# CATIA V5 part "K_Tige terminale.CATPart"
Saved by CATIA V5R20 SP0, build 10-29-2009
Part number: Tige terminale
Property "Diamètre joint": 20 mm
Bounding box of the stored display mesh (mm): x -19.98 to 19.98, y -10 to 10, z 0 to 740
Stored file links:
  C:\Users\thinkmotion1\Desktop\Khaled_IAO_Pack2\Problemes\IAO_2010_1405_jpalas\IAO_PALAS\Khaled_Palas\K_Tige terminale.CATPart
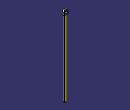
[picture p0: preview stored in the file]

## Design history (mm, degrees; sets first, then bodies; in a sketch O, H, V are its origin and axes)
Body1 (main body)
  Sketch1 on zx-plane, origin (0, 0, 0), H (0, 0, 1), V (1, 0, 0)
    point P1 (740, 0)
    line L1 (740, 0) -> (0, 0)
    line L2 (0, 0) -> (0, 10)
    line L3 (0, 10) -> (700, 10)
    line L4 (700, 10) -> (700, 20)
    line L5 (700, 20) -> (720, 20)
    arc A1 centre (720, 0) radius 20 from (740, 0) to (720, 20) ccw
    point P7 (720, 0)
    length L5 = 20
    length L3 = 700
    distance L3 L1 = 10
    distance L5 L1 = 20
    radius A1 = 20
    coincidence: P1 H, P7 L1, L2 V
    horizontal: L1 H, L3 H, L5 H
    vertical: L2 V, L4 V
  Shaft1: profile Sketch1, axis Sketch1.L1, angle 360
  Sketch2 on face of Shaft1 from Sketch1.L4, origin (10, 0, 700), H (1, 0, 0), V (0, 1, 0)
    line L1 (10, 20) -> (-30, 20)
    line L2 (-30, 20) -> (-30, 10)
    line L3 (-30, 10) -> (10, 10)
    line L4 (10, 10) -> (10, 20)
    reference projected circle E1 centre (-10, 0) radius 10 from edge [face of Shaft1 from Sketch1.L3 | face of Shaft1 from Sketch1.L4]
    reference projected circle E2 centre (-10, 0) radius 20 from edge [face of Shaft1 from Sketch1.L4 | face of Shaft1 from Sketch1.L5]
    reference projected circle E3 centre (-10, 0) radius 20 from edge [face of Shaft1 from Sketch1.L4 | face of Shaft1 from Sketch1.L5]
    reference projected circle E4 centre (-10, 0) radius 20 from edge [face of Shaft1 from Sketch1.L4 | face of Shaft1 from Sketch1.L5]
    line L5 (10, -10) -> (-30, -10)
    line L6 (-30, -10) -> (-30, -20)
    line L7 (-30, -20) -> (10, -20)
    line L8 (10, -20) -> (10, -10)
    reference projected circle E5 centre (-10, 0) radius 20 from edge [face of Shaft1 from Sketch1.L4 | face of Shaft1 from Sketch1.L5]
    reference projected circle E6 centre (-10, 0) radius 20 from edge [face of Shaft1 from Sketch1.L4 | face of Shaft1 from Sketch1.L5]
    reference projected circle E7 centre (-10, 0) radius 10 from edge [face of Shaft1 from Sketch1.L3 | face of Shaft1 from Sketch1.L4]
    reference projected circle E8 centre (-10, 0) radius 20 from edge [face of Shaft1 from Sketch1.L4 | face of Shaft1 from Sketch1.L5]
    horizontal: L1 H, L3 H, L5 H, L7 H
    vertical: L2 V, L4 V, L6 V, L8 V
    tangency: L3 E1, L1 E2, L4 E3, L2 E4, L6 E5, L8 E6, E7 L5, L7 E8
  Pocket1: profile Sketch2, direction (0, 0, 1), length 40
  Sketch3 on face of Pocket1 from Sketch2.L3, origin (0.467, 10, 725.6191), H (1, 0, 0), V (0, 0, -1)
    point P1 (-0.467, 5.6191)
    reference projected arc E1 centre (-0.467, 5.6191) radius 17.3205 from (-17.7875, 5.6191) to (16.8535, 5.6191) ccw from edge [face of Pocket1 from Sketch2.L3 | face of Shaft1 from Sketch1.A1]
    concentricity: P1 E1
  Hole1: placed by Sketch3, at (0, 10, 720) direction (0, -1, 0), diameter 20, through (limit type 3)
